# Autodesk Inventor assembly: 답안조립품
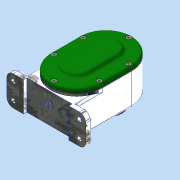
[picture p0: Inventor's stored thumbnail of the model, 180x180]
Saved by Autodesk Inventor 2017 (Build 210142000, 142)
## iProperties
Part Number: 답안조립품
Material: 일반
Document SubType Name: Assembly
Designer: MRC
Author: MRC
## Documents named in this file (19)
- C:\Users\MRC\Desktop\710609V1003\답안조립품.iam
- C:\Users\MRC\Desktop\710609V1003\본체.ipt
- C:\Users\MRC\Desktop\710609V1003\개스킷 A.ipt
- C:\Users\MRC\Desktop\710609V1003\개스킷 B.ipt
- C:\Users\MRC\Desktop\710609V1003\베어링 6001.ipt
- 베어링 6001.ipt
- C:\Users\MRC\Desktop\710609V1003\베어링 6002.ipt
- 베어링 6002.ipt
- C:\Users\MRC\Desktop\710609V1003\볼트 M4.ipt
- C:\Users\MRC\Desktop\710609V1003\스퍼기어 A.ipt
- C:\Users\MRC\Desktop\710609V1003\스퍼기어 B.ipt
- C:\Users\MRC\Desktop\710609V1003\오일 실 12 22 7.ipt
- C:\Users\MRC\Desktop\710609V1003\축 A.ipt
- C:\Users\MRC\Desktop\710609V1003\축 B.ipt
- C:\Users\MRC\Desktop\710609V1003\칼라.ipt
- C:\Users\MRC\Desktop\710609V1003\커버 A.ipt
- C:\Users\MRC\Desktop\710609V1003\커버 B.ipt
- C:\Users\MRC\Desktop\710609V1003\키 4 x 4 x 12.ipt
- C:\Users\MRC\Desktop\710609V1003\키 5 x 5 x 12.ipt
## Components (2 placed, 2 different names)
1. 개스킷 A:1
2. 개스킷 B:1
